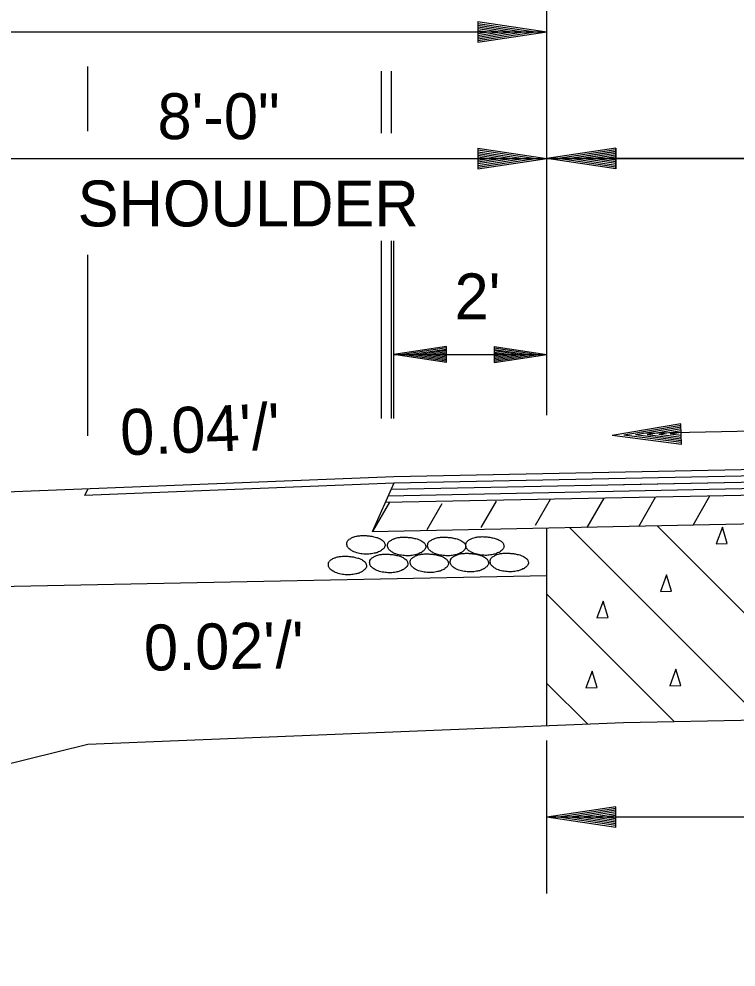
# Model space of a CAD drawing. Extents: x 634177 to 635904, y 289936 to 290970.
# Drawn here: x 635831.78 to 635841.15, y 290605.63 to 290618.02 of the extents above; entities that cross this region are included whole.
import ezdxf

# ---------------------------------------------------------------- set-up
doc = ezdxf.new("R2010")
doc.units = 0
for name, color, linetype in [('1', 7, 'Continuous'), ('4', 7, 'Continuous'), ('Default', 7, 'Continuous')]:
    doc.layers.add(name, color=color, linetype=linetype)

msp = doc.modelspace()

# ---------------------------------------------------------------- linework, layer by layer
at = {"layer": '1'}
for p, q in [((635840.121, 290611.391), (635842.635, 290608.877)), ((635838.977, 290611.368), (635841.491, 290608.854)), ((635838.678, 290610.501), (635840.347, 290608.831)), ((635838.678, 290609.334), (635839.213, 290608.799))]:
    msp.add_line(p, q, dxfattribs=at)
at = {"layer": '4'}
for points in [[(635840.972, 290611.377), (635840.892, 290611.158), (635841.037, 290611.163), (635840.972, 290611.377)], [(635840.242, 290610.752), (635840.162, 290610.533), (635840.307, 290610.538), (635840.242, 290610.752)], [(635839.413, 290610.408), (635839.332, 290610.19), (635839.478, 290610.195), (635839.413, 290610.408)], [(635840.366, 290609.521), (635840.286, 290609.302), (635840.431, 290609.308), (635840.366, 290609.521)], [(635839.27, 290609.492), (635839.189, 290609.274), (635839.335, 290609.279), (635839.27, 290609.492)]]:
    msp.add_lwpolyline(points, dxfattribs=at)
at = {"layer": 'Default'}
for p, q in [((635838.678, 290612.837), (635838.678, 290623.179)), ((635837.778, 290617.981), (635838.678, 290617.846)), ((635837.778, 290617.981), (635837.778, 290617.711)), ((635837.778, 290617.959), (635838.528, 290617.846)), ((635808.678, 290617.846), (635838.678, 290617.846)), ((635837.778, 290617.936), (635838.373, 290617.846)), ((635837.778, 290617.913), (635838.223, 290617.846)), ((635837.778, 290617.89), (635838.07, 290617.846)), ((635837.778, 290617.867), (635837.92, 290617.846)), ((635837.778, 290617.711), (635838.678, 290617.846)), ((635837.778, 290617.802), (635838.07, 290617.846)), ((635837.778, 290617.756), (635838.373, 290617.846)), ((635837.778, 290617.734), (635838.528, 290617.846)), ((635837.778, 290617.779), (635838.223, 290617.846)), ((635837.778, 290617.825), (635837.92, 290617.846)), ((635832.678, 290616.551), (635832.678, 290617.393)), ((635836.517, 290616.522), (635836.517, 290617.334)), ((635836.649, 290616.522), (635836.649, 290617.334)), ((635838.678, 290612.903), (635838.678, 290617.269)), ((635837.778, 290616.328), (635838.678, 290616.193)), ((635837.778, 290616.328), (635837.778, 290616.058)), ((635839.578, 290616.328), (635838.678, 290616.193)), ((635839.579, 290616.328), (635838.679, 290616.193)), ((635839.578, 290616.328), (635839.578, 290616.058)), ((635839.579, 290616.058), (635839.579, 290616.328)), ((635837.778, 290616.306), (635838.528, 290616.193)), ((635837.778, 290616.282), (635838.373, 290616.193)), ((635837.778, 290616.26), (635838.223, 290616.193)), ((635837.778, 290616.236), (635838.07, 290616.193)), ((635837.778, 290616.214), (635837.92, 290616.193)), ((635839.578, 290616.306), (635838.828, 290616.193)), ((635839.579, 290616.306), (635838.829, 290616.193)), ((635839.578, 290616.282), (635838.983, 290616.193)), ((635839.579, 290616.283), (635838.984, 290616.193)), ((635839.578, 290616.26), (635839.133, 290616.193)), ((635839.579, 290616.26), (635839.134, 290616.193)), ((635839.578, 290616.236), (635839.285, 290616.193)), ((635839.579, 290616.237), (635839.286, 290616.193)), ((635839.578, 290616.214), (635839.436, 290616.193)), ((635839.579, 290616.215), (635839.437, 290616.193)), ((635822.398, 290616.193), (635838.678, 290616.193)), ((635837.778, 290616.058), (635838.678, 290616.193)), ((635837.778, 290616.149), (635838.07, 290616.193)), ((635837.778, 290616.103), (635838.373, 290616.193)), ((635837.778, 290616.081), (635838.528, 290616.193)), ((635837.778, 290616.126), (635838.223, 290616.193)), ((635837.778, 290616.172), (635837.92, 290616.193)), ((635850.678, 290616.193), (635838.678, 290616.193)), ((635839.578, 290616.058), (635838.678, 290616.193)), ((635838.678, 290616.193), (635850.678, 290616.193)), ((635839.579, 290616.058), (635838.679, 290616.193)), ((635839.578, 290616.081), (635838.828, 290616.193)), ((635839.579, 290616.081), (635838.829, 290616.193)), ((635839.578, 290616.103), (635838.983, 290616.193)), ((635839.579, 290616.103), (635838.984, 290616.193)), ((635839.578, 290616.126), (635839.133, 290616.193)), ((635839.579, 290616.127), (635839.134, 290616.193)), ((635839.578, 290616.149), (635839.285, 290616.193)), ((635839.579, 290616.15), (635839.286, 290616.193)), ((635839.578, 290616.172), (635839.436, 290616.193)), ((635839.579, 290616.172), (635839.437, 290616.193)), ((635836.517, 290612.797), (635836.517, 290615.119)), ((635836.649, 290612.797), (635836.649, 290615.119)), ((635836.678, 290612.797), (635836.678, 290615.119)), ((635832.678, 290612.569), (635832.678, 290614.936)), ((635837.368, 290613.734), (635836.678, 290613.631)), ((635837.368, 290613.527), (635837.368, 290613.734)), ((635837.988, 290613.734), (635838.678, 290613.631)), ((635837.988, 290613.734), (635837.988, 290613.527)), ((635836.678, 290613.631), (635838.678, 290613.631)), ((635837.368, 290613.527), (635836.678, 290613.631)), ((635837.368, 290613.717), (635836.793, 290613.631)), ((635837.368, 290613.545), (635836.793, 290613.631)), ((635837.368, 290613.699), (635836.912, 290613.631)), ((635837.368, 290613.562), (635836.912, 290613.631)), ((635837.368, 290613.682), (635837.027, 290613.631)), ((635837.368, 290613.579), (635837.027, 290613.631)), ((635837.368, 290613.665), (635837.144, 290613.631)), ((635837.368, 290613.597), (635837.144, 290613.631)), ((635837.368, 290613.647), (635837.259, 290613.631)), ((635837.368, 290613.615), (635837.259, 290613.631)), ((635837.988, 290613.717), (635838.563, 290613.631)), ((635837.988, 290613.699), (635838.444, 290613.631)), ((635837.988, 290613.682), (635838.329, 290613.631)), ((635837.988, 290613.664), (635838.212, 290613.631)), ((635837.988, 290613.647), (635838.097, 290613.631)), ((635837.988, 290613.527), (635838.678, 290613.631)), ((635837.988, 290613.597), (635838.212, 290613.631)), ((635837.988, 290613.562), (635838.444, 290613.631)), ((635837.988, 290613.545), (635838.563, 290613.631)), ((635837.988, 290613.579), (635838.329, 290613.631)), ((635837.988, 290613.615), (635838.097, 290613.631)), ((635840.431, 290612.727), (635839.534, 290612.574)), ((635840.432, 290612.704), (635839.685, 290612.577)), ((635840.432, 290612.681), (635839.839, 290612.58)), ((635841.376, 290612.628), (635839.919, 290612.599)), ((635840.434, 290612.659), (635839.99, 290612.583)), ((635840.433, 290612.636), (635840.142, 290612.585)), ((635840.433, 290612.613), (635840.292, 290612.589)), ((635840.437, 290612.457), (635840.431, 290612.727)), ((635840.437, 290612.457), (635839.534, 290612.574)), ((635840.437, 290612.48), (635839.685, 290612.577)), ((635840.436, 290612.502), (635839.839, 290612.58)), ((635840.435, 290612.525), (635839.99, 290612.583)), ((635840.435, 290612.548), (635840.142, 290612.585)), ((635840.435, 290612.571), (635840.292, 290612.589)), ((635850.678, 290612.314), (635836.678, 290612.034)), ((635850.678, 290612.148), (635836.64, 290611.867)), ((635850.678, 290612.231), (635836.678, 290611.951)), ((635850.678, 290612.148), (635839.68, 290611.928)), ((635836.678, 290612.034), (635830.678, 290611.794)), ((635850.678, 290612.078), (635836.601, 290611.779)), ((635836.678, 290611.951), (635832.635, 290611.789)), ((635832.678, 290611.874), (635832.635, 290611.789)), ((635836.678, 290611.951), (635836.394, 290611.316)), ((635850.678, 290611.978), (635836.565, 290611.699)), ((635839.207, 290611.373), (635839.428, 290611.755)), ((635839.88, 290611.386), (635840.1, 290611.769)), ((635840.589, 290611.4), (635840.81, 290611.783)), ((635836.404, 290611.317), (635836.625, 290611.7)), ((635837.113, 290611.345), (635837.31, 290611.686)), ((635837.822, 290611.373), (635838.019, 290611.715)), ((635838.531, 290611.402), (635838.728, 290611.742)), ((635850.678, 290611.603), (635836.394, 290611.316)), ((635838.678, 290608.778), (635838.678, 290611.362)), ((635838.678, 290610.74), (635822.398, 290610.414)), ((635850.678, 290609.038), (635839.68, 290608.818)), ((635839.68, 290608.818), (635832.678, 290608.537)), ((635832.678, 290608.537), (635821.036, 290605.627)), ((635838.678, 290606.587), (635838.678, 290608.587)), ((635839.579, 290607.722), (635838.679, 290607.587)), ((635839.579, 290607.7), (635838.829, 290607.587)), ((635839.579, 290607.677), (635838.984, 290607.587)), ((635839.579, 290607.452), (635839.579, 290607.722)), ((635862.678, 290607.587), (635838.678, 290607.587)), ((635839.579, 290607.452), (635838.679, 290607.587)), ((635839.579, 290607.475), (635838.829, 290607.587)), ((635839.579, 290607.497), (635838.984, 290607.587)), ((635839.579, 290607.654), (635839.134, 290607.587)), ((635839.579, 290607.52), (635839.134, 290607.587)), ((635839.579, 290607.631), (635839.286, 290607.587)), ((635839.579, 290607.544), (635839.286, 290607.587)), ((635839.579, 290607.609), (635839.437, 290607.587)), ((635839.579, 290607.565), (635839.437, 290607.587))]:
    msp.add_line(p, q, dxfattribs=at)
msp.add_lwpolyline([(635838.678, 290610.74), (635838.678, 290611.362)], dxfattribs=at)
for points in [[(635836.546, 290611.189), (635836.556, 290611.172), (635836.561, 290611.157), (635836.565, 290611.137), (635836.562, 290611.125), (635836.552, 290611.106), (635836.54, 290611.091), (635836.519, 290611.075), (635836.505, 290611.063), (635836.493, 290611.059), (635836.467, 290611.046), (635836.422, 290611.034), (635836.354, 290611.023), (635836.285, 290611.024), (635836.212, 290611.036), (635836.139, 290611.062), (635836.097, 290611.091), (635836.071, 290611.122), (635836.065, 290611.147), (635836.066, 290611.17), (635836.074, 290611.194), (635836.083, 290611.205), (635836.097, 290611.217), (635836.115, 290611.227), (635836.136, 290611.24), (635836.153, 290611.246), (635836.186, 290611.257), (635836.233, 290611.264), (635836.297, 290611.266), (635836.344, 290611.262), (635836.392, 290611.256), (635836.417, 290611.25), (635836.451, 290611.242), (635836.49, 290611.227), (635836.512, 290611.215), (635836.539, 290611.195), (635836.551, 290611.184)], [(635838.1, 290611.174), (635838.11, 290611.157), (635838.115, 290611.142), (635838.119, 290611.122), (635838.116, 290611.11), (635838.106, 290611.091), (635838.094, 290611.076), (635838.073, 290611.06), (635838.059, 290611.048), (635838.047, 290611.044), (635838.021, 290611.031), (635837.976, 290611.019), (635837.908, 290611.008), (635837.839, 290611.009), (635837.766, 290611.021), (635837.693, 290611.047), (635837.651, 290611.076), (635837.625, 290611.107), (635837.619, 290611.132), (635837.62, 290611.155), (635837.628, 290611.179), (635837.637, 290611.19), (635837.651, 290611.202), (635837.669, 290611.212), (635837.69, 290611.225), (635837.707, 290611.231), (635837.74, 290611.242), (635837.787, 290611.249), (635837.851, 290611.251), (635837.898, 290611.247), (635837.946, 290611.241), (635837.971, 290611.235), (635838.005, 290611.227), (635838.044, 290611.212), (635838.066, 290611.2), (635838.093, 290611.18), (635838.105, 290611.169)], [(635837.078, 290611.168), (635837.088, 290611.151), (635837.093, 290611.136), (635837.097, 290611.116), (635837.094, 290611.104), (635837.084, 290611.085), (635837.072, 290611.07), (635837.051, 290611.054), (635837.037, 290611.042), (635837.025, 290611.038), (635836.999, 290611.025), (635836.954, 290611.013), (635836.886, 290611.002), (635836.817, 290611.003), (635836.744, 290611.015), (635836.671, 290611.041), (635836.629, 290611.07), (635836.603, 290611.101), (635836.597, 290611.126), (635836.598, 290611.149), (635836.606, 290611.173), (635836.615, 290611.184), (635836.629, 290611.196), (635836.647, 290611.206), (635836.668, 290611.219), (635836.685, 290611.225), (635836.718, 290611.236), (635836.765, 290611.243), (635836.829, 290611.245), (635836.876, 290611.241), (635836.924, 290611.235), (635836.949, 290611.229), (635836.983, 290611.221), (635837.022, 290611.206), (635837.044, 290611.194), (635837.071, 290611.174), (635837.083, 290611.163)], [(635837.601, 290611.168), (635837.611, 290611.151), (635837.616, 290611.136), (635837.62, 290611.116), (635837.617, 290611.104), (635837.607, 290611.085), (635837.595, 290611.07), (635837.574, 290611.054), (635837.56, 290611.042), (635837.548, 290611.038), (635837.522, 290611.025), (635837.477, 290611.013), (635837.409, 290611.002), (635837.34, 290611.003), (635837.267, 290611.015), (635837.194, 290611.041), (635837.152, 290611.07), (635837.126, 290611.101), (635837.12, 290611.126), (635837.121, 290611.149), (635837.129, 290611.173), (635837.138, 290611.184), (635837.152, 290611.196), (635837.17, 290611.206), (635837.191, 290611.219), (635837.208, 290611.225), (635837.241, 290611.236), (635837.288, 290611.243), (635837.352, 290611.245), (635837.399, 290611.241), (635837.447, 290611.235), (635837.472, 290611.229), (635837.506, 290611.221), (635837.545, 290611.206), (635837.567, 290611.194), (635837.594, 290611.174), (635837.606, 290611.163)], [(635836.844, 290610.946), (635836.854, 290610.929), (635836.859, 290610.914), (635836.863, 290610.894), (635836.86, 290610.882), (635836.85, 290610.863), (635836.838, 290610.848), (635836.817, 290610.832), (635836.803, 290610.82), (635836.791, 290610.816), (635836.765, 290610.803), (635836.72, 290610.791), (635836.652, 290610.78), (635836.583, 290610.781), (635836.51, 290610.793), (635836.437, 290610.819), (635836.395, 290610.848), (635836.369, 290610.879), (635836.363, 290610.904), (635836.364, 290610.927), (635836.372, 290610.951), (635836.381, 290610.962), (635836.395, 290610.974), (635836.413, 290610.984), (635836.434, 290610.997), (635836.451, 290611.003), (635836.484, 290611.014), (635836.531, 290611.021), (635836.595, 290611.023), (635836.642, 290611.019), (635836.69, 290611.013), (635836.715, 290611.007), (635836.749, 290610.999), (635836.788, 290610.984), (635836.81, 290610.972), (635836.837, 290610.952), (635836.849, 290610.941)], [(635837.374, 290610.949), (635837.384, 290610.932), (635837.389, 290610.917), (635837.393, 290610.897), (635837.39, 290610.885), (635837.38, 290610.866), (635837.368, 290610.851), (635837.347, 290610.835), (635837.333, 290610.823), (635837.321, 290610.819), (635837.295, 290610.806), (635837.25, 290610.794), (635837.182, 290610.783), (635837.113, 290610.784), (635837.04, 290610.796), (635836.967, 290610.822), (635836.925, 290610.851), (635836.899, 290610.882), (635836.893, 290610.907), (635836.894, 290610.93), (635836.902, 290610.954), (635836.911, 290610.965), (635836.925, 290610.977), (635836.943, 290610.987), (635836.964, 290611), (635836.981, 290611.006), (635837.014, 290611.017), (635837.061, 290611.024), (635837.125, 290611.026), (635837.172, 290611.022), (635837.22, 290611.016), (635837.245, 290611.01), (635837.279, 290611.002), (635837.318, 290610.987), (635837.34, 290610.975), (635837.367, 290610.955), (635837.379, 290610.944)], [(635837.898, 290610.957), (635837.908, 290610.94), (635837.913, 290610.925), (635837.917, 290610.905), (635837.914, 290610.893), (635837.904, 290610.874), (635837.892, 290610.859), (635837.871, 290610.843), (635837.857, 290610.831), (635837.845, 290610.827), (635837.819, 290610.814), (635837.774, 290610.802), (635837.706, 290610.791), (635837.637, 290610.792), (635837.564, 290610.804), (635837.491, 290610.83), (635837.449, 290610.859), (635837.423, 290610.89), (635837.417, 290610.915), (635837.418, 290610.938), (635837.426, 290610.962), (635837.435, 290610.973), (635837.449, 290610.985), (635837.467, 290610.995), (635837.488, 290611.008), (635837.505, 290611.014), (635837.538, 290611.025), (635837.585, 290611.032), (635837.649, 290611.034), (635837.696, 290611.03), (635837.744, 290611.024), (635837.769, 290611.018), (635837.803, 290611.01), (635837.842, 290610.995), (635837.864, 290610.983), (635837.891, 290610.963), (635837.903, 290610.952)], [(635838.419, 290610.959), (635838.429, 290610.942), (635838.434, 290610.927), (635838.438, 290610.907), (635838.435, 290610.895), (635838.425, 290610.876), (635838.413, 290610.861), (635838.392, 290610.845), (635838.378, 290610.833), (635838.366, 290610.829), (635838.34, 290610.816), (635838.295, 290610.804), (635838.227, 290610.793), (635838.158, 290610.794), (635838.085, 290610.806), (635838.012, 290610.832), (635837.97, 290610.861), (635837.944, 290610.892), (635837.938, 290610.917), (635837.939, 290610.94), (635837.947, 290610.964), (635837.956, 290610.975), (635837.97, 290610.987), (635837.988, 290610.997), (635838.009, 290611.01), (635838.026, 290611.016), (635838.059, 290611.027), (635838.106, 290611.034), (635838.17, 290611.036), (635838.217, 290611.032), (635838.265, 290611.026), (635838.29, 290611.02), (635838.324, 290611.012), (635838.363, 290610.997), (635838.385, 290610.985), (635838.412, 290610.965), (635838.424, 290610.954)], [(635836.304, 290610.919), (635836.314, 290610.902), (635836.319, 290610.887), (635836.323, 290610.867), (635836.32, 290610.855), (635836.31, 290610.836), (635836.298, 290610.821), (635836.277, 290610.805), (635836.263, 290610.793), (635836.251, 290610.789), (635836.225, 290610.776), (635836.18, 290610.764), (635836.112, 290610.753), (635836.043, 290610.754), (635835.97, 290610.766), (635835.897, 290610.792), (635835.855, 290610.821), (635835.829, 290610.852), (635835.823, 290610.877), (635835.824, 290610.9), (635835.832, 290610.924), (635835.841, 290610.935), (635835.855, 290610.947), (635835.873, 290610.957), (635835.894, 290610.97), (635835.911, 290610.976), (635835.944, 290610.987), (635835.991, 290610.994), (635836.055, 290610.996), (635836.102, 290610.992), (635836.15, 290610.986), (635836.175, 290610.98), (635836.209, 290610.972), (635836.248, 290610.957), (635836.27, 290610.945), (635836.297, 290610.925), (635836.309, 290610.914)]]:
    msp.add_spline(points, degree=3, dxfattribs=at)

# ---------------------------------------------------------------- texts
for s, p in [('8\'-0"', (635833.59, 290616.445)), ('SHOULDER', (635832.546, 290615.305)), ("2'", (635837.472, 290614.091))]:
    msp.add_text(s, height=0.6, dxfattribs=at).set_placement(p)
for s, rotation, p in [("0.04'/'", 2.2906, (635833.114, 290612.313)), ("0.02'/'", 1.146, (635833.419, 290609.499))]:
    msp.add_text(s, height=0.6, rotation=rotation, dxfattribs=at).set_placement(p)

doc.saveas('drawing.dxf')
